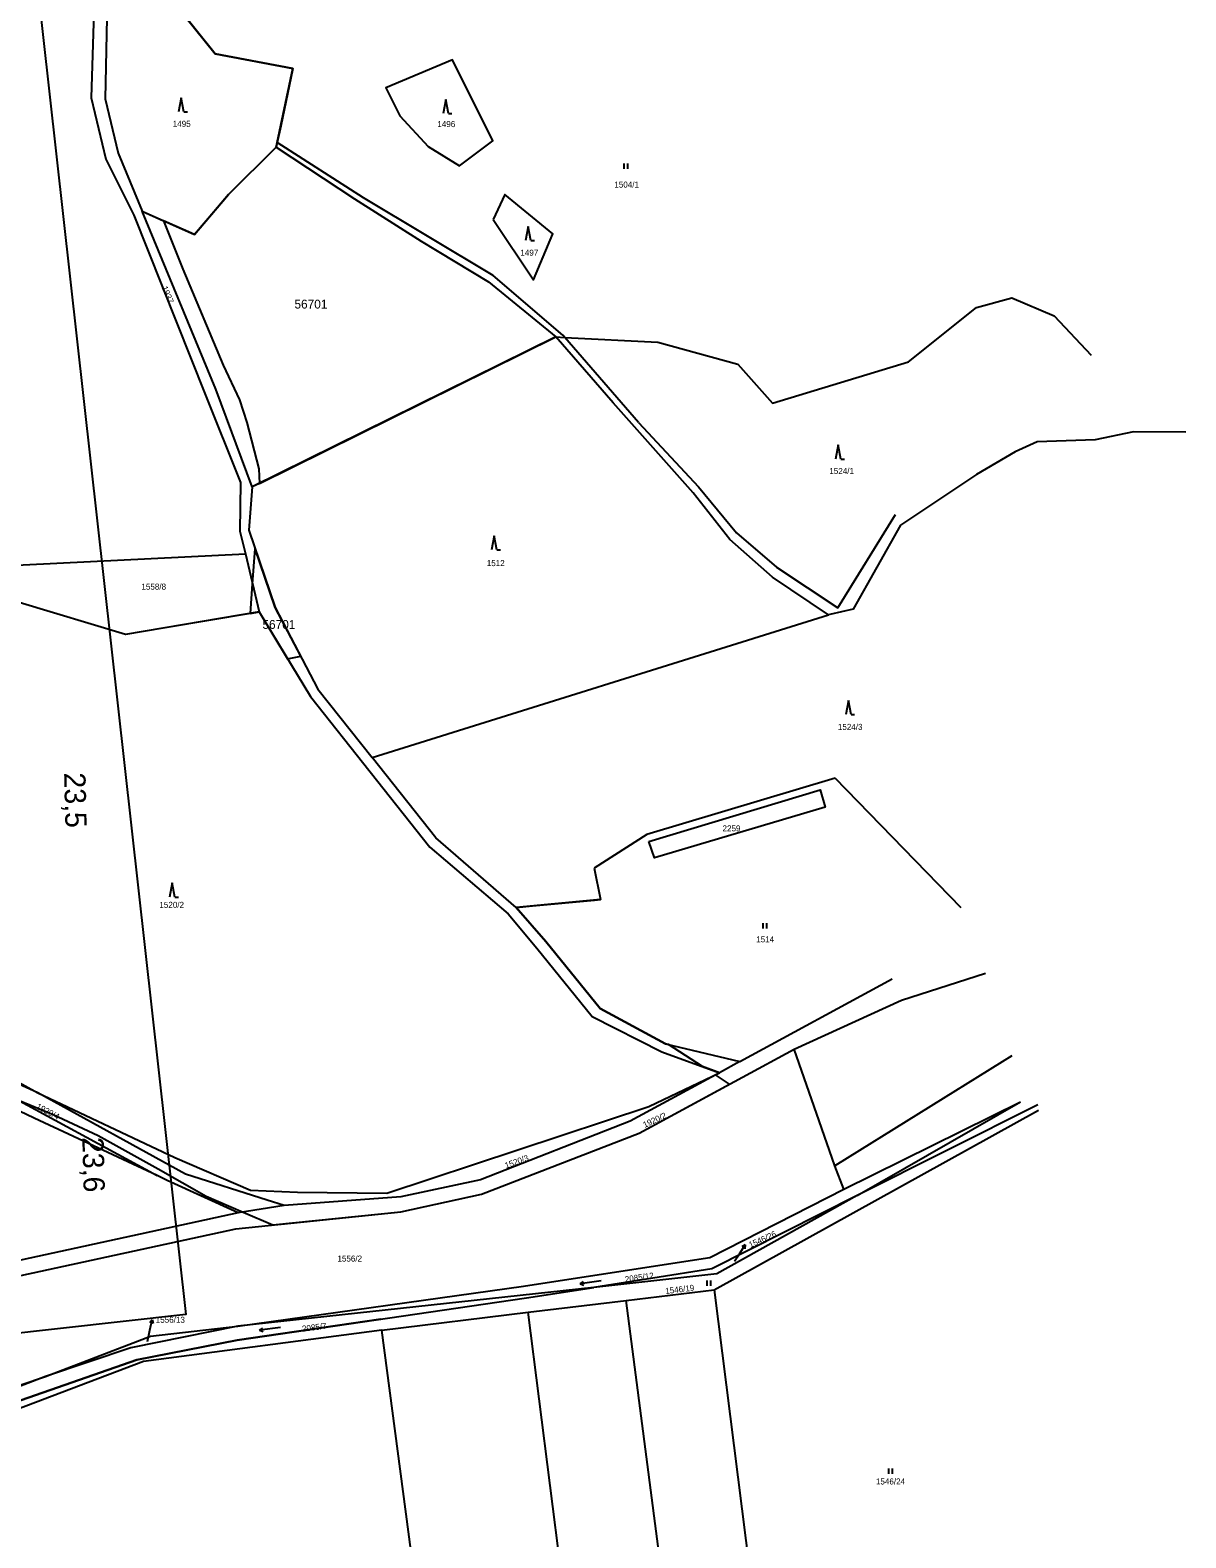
# Model space of a CAD drawing. Extents: x -794765 to -785424, y -1118958 to -1108731.
# Drawn here: x -792465.9 to -792140, y -1111162.6 to -1110737.1 of the extents above; entities that cross this region are included whole.
import ezdxf

# ---------------------------------------------------------------- set-up
doc = ezdxf.new("R2010")
doc.units = 0
for name, color, linetype in [('Level 66', 7, 'Continuous'), ('Level 71', 7, 'Continuous'), ('Level 73', 7, 'Continuous'), ('Level 75', 7, 'Continuous'), ('Level 76', 7, 'Continuous'), ('Level 77', 7, 'Continuous'), ('Level 80', 7, 'Continuous'), ('Level 81', 7, 'Continuous')]:
    doc.layers.add(name, color=color, linetype=linetype)

msp = doc.modelspace()

# ---------------------------------------------------------------- linework, layer by layer
at = {"layer": 'Level 66'}
for p, q in [((-792423.3, -1110756.23), (-792424.05, -1110760.23)), ((-792422.55, -1110760.23), (-792423.3, -1110756.23)), ((-792348.72, -1110756.7), (-792349.47, -1110760.7)), ((-792347.97, -1110760.7), (-792348.72, -1110756.7)), ((-792422.55, -1110760.23), (-792421.55, -1110760.23)), ((-792347.97, -1110760.7), (-792346.97, -1110760.7)), ((-792298.34, -1110776.24), (-792298.34, -1110774.74)), ((-792297.34, -1110776.24), (-792297.34, -1110774.74)), ((-792325.44, -1110792.52), (-792326.19, -1110796.52)), ((-792324.69, -1110796.52), (-792325.44, -1110792.52)), ((-792324.69, -1110796.52), (-792323.69, -1110796.52)), ((-792237.97, -1110854.18), (-792238.72, -1110858.18)), ((-792237.22, -1110858.18), (-792237.97, -1110854.18)), ((-792237.22, -1110858.18), (-792236.22, -1110858.18)), ((-792335.05, -1110879.83), (-792335.8, -1110883.83)), ((-792334.3, -1110883.83), (-792335.05, -1110879.83)), ((-792334.3, -1110883.83), (-792333.3, -1110883.83)), ((-792235.14, -1110926.28), (-792235.89, -1110930.28)), ((-792234.39, -1110930.28), (-792235.14, -1110926.28)), ((-792234.39, -1110930.28), (-792233.39, -1110930.28)), ((-792425.85, -1110977.78), (-792426.6, -1110981.78)), ((-792425.1, -1110981.78), (-792425.85, -1110977.78)), ((-792425.1, -1110981.78), (-792424.1, -1110981.78)), ((-792259.15, -1110990.66), (-792259.15, -1110989.16)), ((-792258.15, -1110990.66), (-792258.15, -1110989.16)), ((-792304.84, -1111090.1), (-792310.78, -1111090.93)), ((-792310.78, -1111090.93), (-792309.88, -1111090.3)), ((-792274.94, -1111091.46), (-792274.94, -1111089.96)), ((-792273.94, -1111091.46), (-792273.94, -1111089.96)), ((-792310.78, -1111090.93), (-792309.74, -1111091.29)), ((-792395.3, -1111103.22), (-792401.24, -1111104.05)), ((-792401.24, -1111104.05), (-792400.34, -1111103.42)), ((-792401.24, -1111104.05), (-792400.2, -1111104.41)), ((-792223.73, -1111144.5), (-792223.73, -1111143)), ((-792222.73, -1111144.5), (-792222.73, -1111143))]:
    msp.add_line(p, q, dxfattribs=at)
at = {"layer": 'Level 71'}
msp.add_lwpolyline([(-792522.06, -1110204.41), (-792422.02, -1111099.6), (-792720.93, -1111133), (-792820.96, -1110237.81)], close=True, dxfattribs=at)
at = {"layer": 'Level 75'}
for p, q in [((-792317.68, -1110823.69), (-792403.33, -1110866.05)), ((-792499.13, -1110889.58), (-792405.22, -1110884.89)), ((-792405.22, -1110884.89), (-792401.29, -1110901.3)), ((-792369.49, -1110942.36), (-792240.75, -1110902.15)), ((-792203.34, -1110984.82), (-792238.88, -1110948.19)), ((-792541.16, -1110994.37), (-792463.74, -1111037.04)), ((-792540.43, -1111000.58), (-792430.06, -1111060.32)), ((-792265.74, -1111028.23), (-792222.8, -1111004.85)), ((-792287.76, -1111025.49), (-792271.45, -1111031.34)), ((-792286.67, -1111023.19), (-792265.74, -1111028.23)), ((-792265.74, -1111028.23), (-792271.45, -1111031.34)), ((-792273, -1111092.58), (-792181.52, -1111041.95)), ((-792236.46, -1111064.25), (-792186.55, -1111039.58)), ((-792232.66, -1111066.04), (-792186.55, -1111039.58)), ((-792181.74, -1111040.37), (-792232.66, -1111066.04)), ((-792236.46, -1111064.25), (-792238.97, -1111057.62)), ((-792394.27, -1111068.8), (-792407.26, -1111070.93)), ((-792407.26, -1111070.93), (-792528.74, -1111097.29)), ((-792306.91, -1111091.93), (-792407.39, -1111102.88)), ((-792297.81, -1111095.6), (-792273, -1111092.58)), ((-792273, -1111092.58), (-792252.78, -1111251.91)), ((-792325.44, -1111098.96), (-792297.81, -1111095.6)), ((-792273.22, -1111285.03), (-792297.81, -1111095.6)), ((-792366.71, -1111103.99), (-792325.44, -1111098.96)), ((-792296.91, -1111323.44), (-792325.44, -1111098.96)), ((-792330.42, -1111377.77), (-792366.71, -1111103.99)), ((-792461.55, -1111117.1), (-792525.05, -1111141.46))]:
    msp.add_line(p, q, dxfattribs=at)
for points in [[(-792444.46, -1110708.81), (-792444.28, -1110733.69), (-792444.74, -1110756.56), (-792441.14, -1110771.81), (-792434.35, -1110788.26)], [(-792391.79, -1110747.98), (-792413.76, -1110743.86), (-792441.32, -1110709.44), (-792444.46, -1110708.81)], [(-792447.94, -1110732.08), (-792448.76, -1110756.25), (-792444.54, -1110773.51), (-792436.65, -1110789.31), (-792416.68, -1110839.64), (-792406.56, -1110864.78), (-792406.75, -1110878.48), (-792405.22, -1110884.89)], [(-792344.83, -1110775.42), (-792335.39, -1110768.36), (-792346.77, -1110745.5), (-792365.59, -1110753.46), (-792361.69, -1110761.3), (-792353.66, -1110769.94), (-792344.83, -1110775.42)], [(-792396.51, -1110770.15), (-792396.23, -1110768.85), (-792391.79, -1110747.98)], [(-792434.35, -1110788.26), (-792419.56, -1110794.81), (-792410.01, -1110783.55), (-792396.51, -1110770.15)], [(-792335.28, -1110790.59), (-792323.93, -1110807.57), (-792318.54, -1110794.62), (-792332.01, -1110783.56), (-792335.28, -1110790.59)], [(-792403.33, -1110866.05), (-792413.59, -1110838.49), (-792434.35, -1110788.26)], [(-792317.68, -1110823.69), (-792315.15, -1110823.83), (-792288.9, -1110825.23), (-792266.34, -1110831.42), (-792256.52, -1110842.45), (-792218.19, -1110830.78), (-792199.01, -1110815.38), (-792189.05, -1110812.67), (-792177.1, -1110817.79), (-792166.62, -1110828.82)], [(-792240.75, -1110902.15), (-792256.52, -1110891.54), (-792268.57, -1110880.91), (-792278.9, -1110867.73), (-792301.47, -1110842.31), (-792317.68, -1110823.69)], [(-792139.95, -1110850.55), (-792154.68, -1110850.49), (-792165.48, -1110852.75), (-792181.87, -1110853.3), (-792188.06, -1110856.17), (-792198.98, -1110862.49), (-792220.39, -1110876.87), (-792233.74, -1110900.55), (-792240.35, -1110902.03), (-792240.75, -1110902.15)], [(-792403.33, -1110866.05), (-792404.22, -1110878.24), (-792396.84, -1110900.08), (-792384.75, -1110923.07), (-792369.49, -1110942.36)], [(-792401.29, -1110901.3), (-792439.04, -1110907.7), (-792499.13, -1110889.58)], [(-792401.29, -1110901.3), (-792386.84, -1110925.19), (-792353.2, -1110967.68), (-792331.14, -1110986.51), (-792322.99, -1110996.18), (-792307.4, -1111015.46), (-792287.76, -1111025.49)], [(-792328.81, -1110984.69), (-792351.51, -1110965.1), (-792369.49, -1110942.36)], [(-792238.88, -1110948.19), (-792291.96, -1110964.14), (-792306.85, -1110973.64)], [(-792291.39, -1110966.06), (-792243.11, -1110951.56), (-792241.72, -1110956.4), (-792289.79, -1110970.74), (-792291.39, -1110966.06)], [(-792306.85, -1110973.64), (-792305.09, -1110982.49), (-792328.81, -1110984.69)], [(-792328.81, -1110984.69), (-792320.46, -1110994.34), (-792305.1, -1111013.27), (-792286.67, -1111023.19)], [(-792463.74, -1111037.04), (-792477.2, -1111030.88), (-792540.43, -1111000.58)], [(-792250.44, -1111024.74), (-792220.19, -1111010.84), (-792196.48, -1111003.27)], [(-792430.06, -1111060.32), (-792464.77, -1111044.16), (-792539.49, -1111008.64)], [(-792523.64, -1111100.49), (-792407.92, -1111075.39), (-792361.39, -1111070.62), (-792338.58, -1111065.63), (-792294.17, -1111048.39), (-792250.44, -1111024.74)], [(-792238.97, -1111057.62), (-792243.39, -1111044.94), (-792250.44, -1111024.74)], [(-792189.03, -1111026.62), (-792191.73, -1111028.29), (-792238.97, -1111057.62)], [(-792463.74, -1111037.04), (-792425.08, -1111055.31), (-792403.75, -1111064.5), (-792390.47, -1111065.03), (-792365.3, -1111065.34), (-792291.42, -1111040.89), (-792271.45, -1111031.34)], [(-792271.45, -1111031.34), (-792296.66, -1111045.04), (-792338.86, -1111061.54), (-792361.36, -1111066.36), (-792394.27, -1111068.8)], [(-792394.27, -1111068.8), (-792399.05, -1111067.28), (-792422.15, -1111059.95), (-792463.74, -1111037.04)], [(-792407.26, -1111070.93), (-792427.32, -1111061.8), (-792430.06, -1111060.32)], [(-792407.39, -1111102.88), (-792326.81, -1111091.56), (-792316.4, -1111089.97), (-792274.21, -1111083.5), (-792236.46, -1111064.25)], [(-792232.66, -1111066.04), (-792272.28, -1111088.1), (-792306.91, -1111091.93)], [(-792232.66, -1111066.04), (-792273.61, -1111086.69), (-792306.91, -1111091.93)], [(-792525.02, -1111143.72), (-792518.75, -1111141.25), (-792515.51, -1111140.14), (-792435.87, -1111112.41), (-792407.53, -1111106.87), (-792325.89, -1111094.91), (-792306.91, -1111091.93)], [(-792407.39, -1111102.88), (-792437.51, -1111108.98), (-792461.55, -1111117.1)], [(-792461.55, -1111117.1), (-792431.95, -1111105.74), (-792407.39, -1111102.88)], [(-792366.71, -1111103.99), (-792433.98, -1111112.84), (-792515.99, -1111144), (-792517.15, -1111145.92)], [(-792520.72, -1111137.19), (-792518.44, -1111136.3), (-792461.55, -1111117.1)]]:
    msp.add_lwpolyline(points, dxfattribs=at)
at = {"layer": 'Level 77'}
for p, q in [((-792396.51, -1110770.15), (-792374.4, -1110784.73)), ((-792371.88, -1110784.48), (-792396.23, -1110768.85)), ((-792374.4, -1110784.73), (-792355.62, -1110796.65)), ((-792335.29, -1110806.37), (-792371.88, -1110784.48)), ((-792355.62, -1110796.65), (-792336.66, -1110808.17)), ((-792336.66, -1110808.17), (-792317.68, -1110823.69)), ((-792315.66, -1110823.24), (-792335.29, -1110806.37)), ((-792315.15, -1110823.83), (-792315.66, -1110823.24)), ((-792294.37, -1110847.83), (-792315.15, -1110823.83)), ((-792294.37, -1110847.83), (-792277.38, -1110866.03)), ((-792277.38, -1110866.03), (-792266.66, -1110878.95)), ((-792238.1, -1110900.12), (-792221.84, -1110873.87)), ((-792266.66, -1110878.95), (-792255.43, -1110888.73)), ((-792255.43, -1110888.73), (-792238.1, -1110900.12))]:
    msp.add_line(p, q, dxfattribs=at)
at = {"layer": 'Level 80'}
for p, q in [((-792265.89, -1111082.42), (-792264.21, -1111079.93)), ((-792264.21, -1111079.93), (-792265.19, -1111080.48)), ((-792264.21, -1111079.93), (-792264.36, -1111081.04)), ((-792267.29, -1111084.49), (-792265.89, -1111082.42)), ((-792431.5, -1111101.06), (-792432.19, -1111101.94)), ((-792432.12, -1111104), (-792431.5, -1111101.06)), ((-792431.5, -1111101.06), (-792431.21, -1111102.15)), ((-792432.81, -1111107.24), (-792432.12, -1111104))]:
    msp.add_line(p, q, dxfattribs=at)
at = {"layer": 'Level 81'}
for points in [[(-792436.22, -1110715.81), (-792441.32, -1110709.44), (-792444.46, -1110708.81), (-792444.28, -1110733.69), (-792444.74, -1110756.56), (-792441.14, -1110771.81), (-792434.35, -1110788.26), (-792428.3, -1110790.94)], [(-792436.22, -1110715.81), (-792419.19, -1110737.08), (-792413.76, -1110743.86), (-792391.79, -1110747.98), (-792395.24, -1110764.21), (-792396.23, -1110768.85), (-792396.51, -1110770.15), (-792410.01, -1110783.55), (-792414.13, -1110788.4), (-792419.56, -1110794.81), (-792428.3, -1110790.94)], [(-792403.81, -1110901.73), (-792439.04, -1110907.7), (-792499.13, -1110889.58), (-792547.75, -1110874.91), (-792547.02, -1110884.64), (-792546.47, -1110891.94), (-792539.9, -1110979.32), (-792542.88, -1110979.67), (-792544.47, -1110966.23), (-792546.44, -1110948.47), (-792552.69, -1110892.25), (-792554.86, -1110872.76), (-792555.3, -1110868.45), (-792561.36, -1110798.02), (-792570.87, -1110718.09)], [(-792428.3, -1110790.94), (-792422.89, -1110804.57), (-792411.52, -1110831.71), (-792406.88, -1110841.46), (-792404.78, -1110847.82), (-792401.42, -1110860.95), (-792401.26, -1110865.03)], [(-792401.26, -1110865.03), (-792317.68, -1110823.69), (-792315.15, -1110823.83)], [(-792401.26, -1110865.03), (-792403.33, -1110866.05), (-792404.22, -1110878.24), (-792402.45, -1110883.48)], [(-792403.81, -1110901.73), (-792403.19, -1110893.38), (-792402.45, -1110883.48)], [(-792403.81, -1110901.73), (-792401.29, -1110901.3), (-792393.29, -1110914.52), (-792389.62, -1110913.81), (-792396.84, -1110900.08), (-792402.45, -1110883.48)], [(-792502.58, -1111021.07), (-792469.43, -1111039.01), (-792468.75, -1111039.28), (-792459.44, -1111043.12), (-792446.75, -1111049.1), (-792429.83, -1111058.48), (-792416.3, -1111066.16), (-792405.82, -1111070.69), (-792397.45, -1111074.32), (-792361.39, -1111070.62), (-792338.58, -1111065.63), (-792294.17, -1111048.39), (-792268.64, -1111034.59), (-792272.64, -1111031.99), (-792271.45, -1111031.34), (-792276.3, -1111029.6), (-792285.84, -1111023.39), (-792286.67, -1111023.19), (-792305.1, -1111013.27), (-792320.46, -1110994.34), (-792328.81, -1110984.69), (-792324.22, -1110984.26), (-792306.75, -1110982.64), (-792305.09, -1110982.49)], [(-792367.04, -1111100.94), (-792407.53, -1111106.87), (-792435.87, -1111112.41), (-792515.51, -1111140.14), (-792518.75, -1111141.25), (-792525.02, -1111143.72), (-792524.99, -1111145.74), (-792505.91, -1111301.51)]]:
    msp.add_lwpolyline(points, dxfattribs=at)

# ---------------------------------------------------------------- texts
at = {"layer": 'Level 73'}
for s, rotation, p in [('23,5', 271.4243, (-792456.35, -1110946.7)), ('23,6', 271.5127, (-792451.23, -1111049.57))]:
    msp.add_text(s, height=6, rotation=rotation, dxfattribs=at).set_placement(p)
at = {"layer": 'Level 76'}
for s, p in [('1495', (-792425.7, -1110764.42)), ('1496', (-792351.07, -1110764.5)), ('1504/1', (-792301.14, -1110781.57)), ('1497', (-792327.65, -1110800.78)), ('1524/1', (-792240.51, -1110862.41)), ('1512', (-792337.13, -1110888.39)), ('1558/8', (-792434.54, -1110895.03)), ('1524/3', (-792238.1, -1110934.61)), ('2259', (-792270.63, -1110963.25)), ('1520/2', (-792429.47, -1110984.83)), ('1514', (-792261.13, -1110994.55)), ('1556/2', (-792379.25, -1111084.65)), ('1556/13', (-792430.5, -1111101.92)), ('1546/24', (-792227.36, -1111147.55))]:
    msp.add_text(s, height=1.7, dxfattribs=at).set_placement(p)
for s, rotation, p in [('1937', 293, (-792428.88, -1110809.78)), ('1920/4', 332, (-792464.39, -1111041.39)), ('1920/2', 25, (-792292.58, -1111046.95)), ('1520/3', 20, (-792331.68, -1111058.43)), ('1546/26', 24, (-792262.77, -1111080.81)), ('2085/12', 8, (-792298.06, -1111090.52)), ('1546/19', 7, (-792286.68, -1111093.83)), ('2085/7', 7, (-792389.13, -1111104.46))]:
    msp.add_text(s, height=1.7, rotation=rotation, dxfattribs=at).set_placement(p)
at = {"layer": 'Level 81'}
for p in [(-792391.37, -1110815.7), (-792400.41, -1110906.1)]:
    msp.add_text('56701', height=2.5, dxfattribs=at).set_placement(p)

doc.saveas('drawing.dxf')
